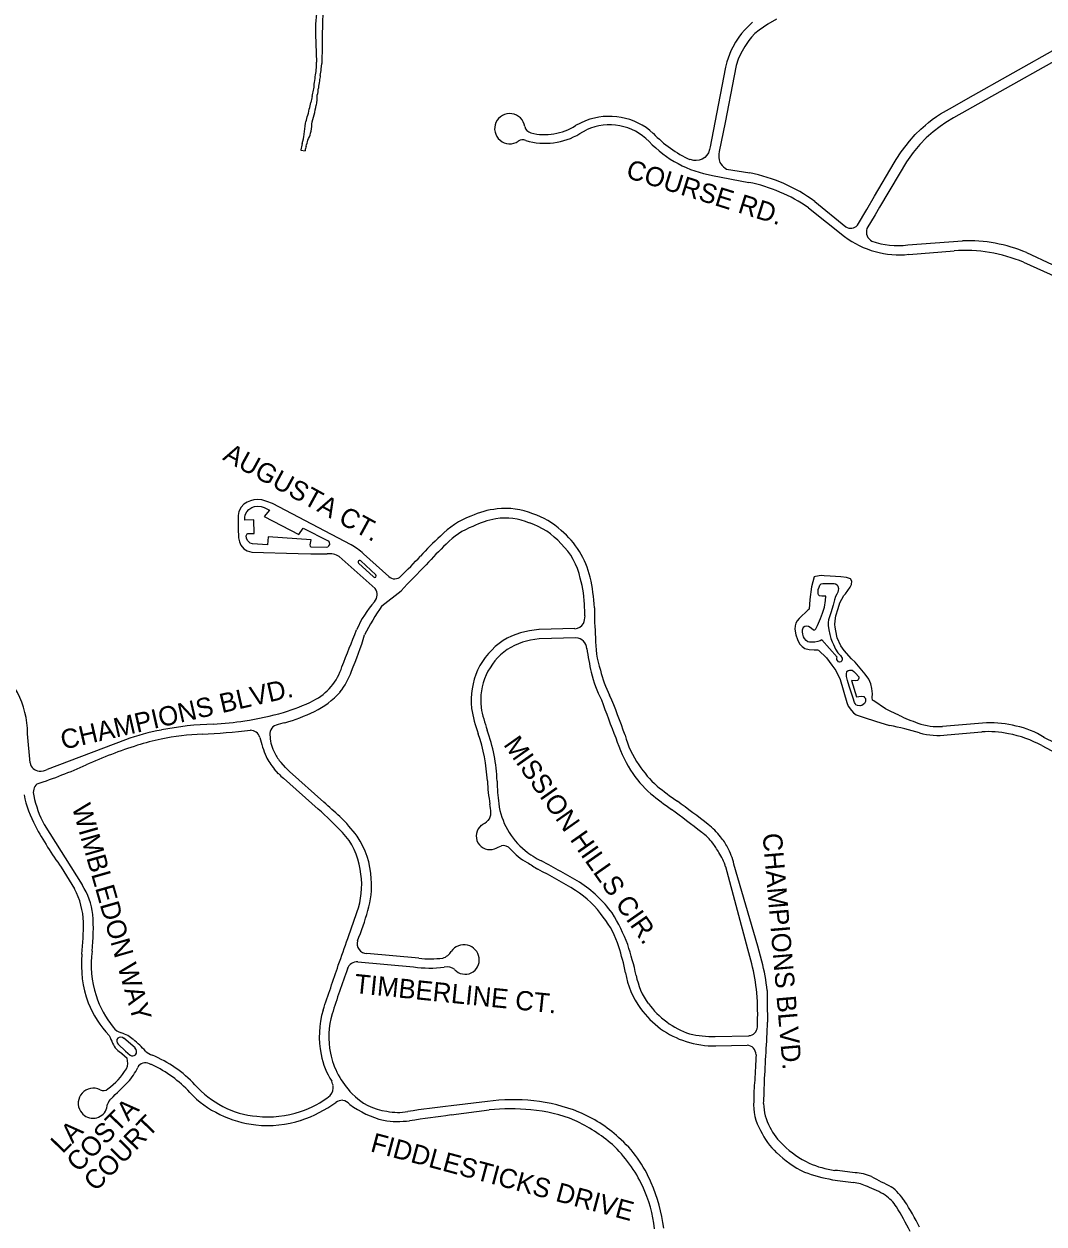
# Model space of a CAD drawing. Extents: x 0 to 712119, y 0 to 761125.
# Drawn here: x 661775 to 664425, y 720502 to 723620 of the extents above; entities that cross this region are included whole.
import ezdxf

# ---------------------------------------------------------------- set-up
doc = ezdxf.new("R2010")
doc.units = 0
doc.layers.add('PAVED ROADS', color=7, linetype='Continuous')
doc.layers.add('street names', color=7, linetype='Continuous')

msp = doc.modelspace()

# ---------------------------------------------------------------- linework, layer by layer
at = {"layer": 'PAVED ROADS'}
for points in [[(665392.5, 724053.4), (664578.7, 723594.7), (664190.1, 723375.9), (664170.3, 723364), (664155.6, 723353.4), (664137, 723340), (664119, 723324), (664102.5, 723306.5), (664085.5, 723286.5), (664067.5, 723261.5), (664048.5, 723230), (663998, 723144.5), (663986, 723124.5), (663965, 723088.5)], [(663668, 723625), (663655.5, 723612.5), (663647, 723604), (663639.5, 723595.5), (663632.5, 723586), (663623.5, 723572.5), (663616.5, 723560), (663611.5, 723550), (663607.5, 723541), (663604.5, 723531), (663601, 723521.5), (663597.5, 723508), (663570, 723364.5), (663557.5, 723301), (663556, 723293.5), (663553.5, 723285.5), (663549, 723279), (663544, 723273.5), (663536.5, 723268.5), (663529.5, 723266), (663521.5, 723265), (663515.5, 723265), (663505.3, 723267.6)], [(663729.6, 723632.3), (663707.8, 723619.7), (663695.9, 723612.1), (663684.6, 723603.6), (663673.9, 723594.9), (663665.4, 723585.9), (663658, 723577.2), (663647.5, 723561.5), (663637.3, 723543.2), (663630.6, 723528.6), (663625.5, 723512.1), (663619.7, 723485.4), (663596.5, 723364.5), (663581.5, 723289), (663580, 723282), (663580, 723273), (663581, 723267), (663583, 723260.5), (663585.5, 723256.5), (663588.5, 723252.5), (663592, 723248.5), (663597, 723245), (663600.5, 723243)], [(663940.5, 723097), (663965, 723138), (663985, 723173), (664036, 723259.5), (664041.1, 723268.2), (664054, 723288), (664066.5, 723304.5), (664075.5, 723315.5), (664090.5, 723333), (664105, 723347), (664116.8, 723357.2), (664124.9, 723364), (664134.4, 723371.7), (664145.6, 723379.6), (664155.8, 723386.8), (664179.1, 723400), (664205.7, 723414.4), (664227.7, 723427.6), (664578.6, 723624.7)], [(662532, 723592.5), (662535, 723520.5)], [(662547, 723503), (662549.1, 723517.2)], [(663233.8, 723368.6), (663208, 723356)], [(663219, 723335.2), (663236.6, 723345.1)], [(662494.2, 723292.3), (662505.5, 723290.5)], [(663600.5, 723243), (663660.5, 723233)], [(663564, 723226.5), (663658.5, 723208.5)], [(663829.5, 723159), (663910, 723093)], [(663813, 723142.5), (663907, 723067.5)], [(664071, 723046), (664213.5, 723056.5)], [(664074, 723021.5), (664191.5, 723031)], [(664379.5, 723026), (664512.5, 722964)], [(664372, 723001), (664510.5, 722939)], [(662625, 722267), (662420.5, 722374), (662406, 722379.5), (662393, 722383.5), (662382, 722384.5), (662372, 722383.5), (662363.5, 722381.5), (662354.5, 722377.5), (662346.5, 722372.5), (662339, 722364.5), (662333, 722353), (662331, 722343), (662331, 722330.5), (662331.5, 722310.5), (662332.5, 722285), (662334.5, 722275), (662338.5, 722265.5), (662346, 722256.5), (662355, 722251.5), (662366.5, 722247.5), (662487.5, 722244), (662520.5, 722243), (662562.5, 722243.5)], [(662722.5, 722184.5), (662657, 722243.5)], [(662594, 722236.5), (662687, 722153.5)], [(662683.1, 722183.3), (662644.2, 722218.9)], [(662649.9, 722225.1), (662689.1, 722189.2)], [(664048, 721824), (664027, 721833.5), (664013, 721840.5), (663983, 721861.5), (663979.5, 721863.5), (663978.5, 721870), (663979.5, 721879.5), (663977.5, 721893.5), (663975, 721905.5), (663970, 721917.5), (663960, 721931), (663947.5, 721946.5), (663934.5, 721961.5), (663924.5, 721971), (663906, 721992.5), (663897, 722004.5), (663888, 722025.5), (663884, 722043), (663882.5, 722052.5), (663882, 722059.5), (663882.5, 722069.5), (663884.5, 722082.5), (663890, 722101), (663895, 722116), (663899.5, 722125.5), (663905, 722135.5), (663909, 722139.5), (663921, 722156.5), (663925, 722164), (663926, 722172.5), (663922.7, 722178.5), (663911.5, 722182), (663897, 722183.5), (663869.5, 722185), (663853.5, 722186), (663846, 722187.5), (663831, 722184.5), (663827.5, 722183.5), (663821, 722157.5), (663817, 722124.5), (663814.5, 722100), (663812.5, 722097.5), (663788.5, 722075.5), (663784, 722069), (663780.5, 722063.5), (663778.5, 722056), (663778, 722047.5), (663780.5, 722033), (663784.5, 722020.5), (663790, 722009.5), (663796.5, 722003), (663804, 721997.5), (663815, 721995), (663828, 721994), (663836.5, 721994), (663839, 721993), (663859.5, 721973.5), (663873.5, 721954.5), (663884, 721940.5), (663895.5, 721916.5), (663913, 721857.5), (663916.5, 721848), (663924.5, 721836), (663930, 721830.5), (663937, 721825.5), (663957.5, 721818.5), (663987, 721808.5), (664024, 721797)], [(662705, 722108), (662754.5, 722147.5)], [(663206.5, 722049), (663113, 722046.5)], [(663209, 722025.5), (663113, 722022.5)], [(661791, 721700), (661784.5, 721776)], [(664276, 721804.5), (664161.5, 721795)], [(664173.5, 721773), (664263.5, 721781)], [(662038.5, 721760), (661835.5, 721683)], [(664419.5, 721745), (664482.5, 721711.5)], [(664512, 721724), (664425, 721766.5)], [(662436.6, 721672.2), (662425.3, 721685)], [(662454.5, 721688.1), (662443.1, 721700.9)], [(662539.5, 721580), (662449, 721660.3)], [(662553.6, 721598.2), (662465, 721678)], [(661827.4, 721539.8), (661926.2, 721383)], [(663692, 721185), (663681.5, 721224), (663619.5, 721437.5)], [(661871.8, 721429.1), (661906.3, 721372.7)], [(663666, 721178.5), (663655.5, 721216.5), (663598, 721429.9)], [(662642.5, 721183), (662787, 721170)], [(662800.5, 721192.5), (662665.5, 721205)], [(662005, 720972), (662005, 720972), (662005, 720972)], [(662020, 720969.5), (662038.9, 720951.4), (662050.5, 720940.5)], [(662063.4, 720960.1), (662034.7, 720984.6)], [(663570.5, 720989), (663658, 720991.5)], [(663572, 720965), (663653.5, 720967)], [(662029.6, 720945.1), (662042.8, 720933.1)], [(662578, 720862.5), (662576.5, 720866.5), (662574.5, 720873)], [(662979, 720820.5), (662884.5, 720809.5)], [(663696.5, 720815), (663696.5, 720815)], [(662884.5, 720785.5), (662983.5, 720799)]]:
    msp.add_lwpolyline(points, dxfattribs=at)
for points in [[(662408, 722267), (662369, 722269), (662362.5, 722271.5), (662356, 722278), (662353, 722284.5), (662352.5, 722290), (662355, 722295), (662356.5, 722296), (662373, 722296.5), (662372, 722332), (662348.5, 722331), (662348.5, 722337.5), (662350, 722344.5), (662353.5, 722352.5), (662359.5, 722359), (662367, 722364), (662374, 722366.5), (662382.5, 722367.5), (662391.5, 722366.5), (662399, 722364), (662412.5, 722356.5), (662399, 722340.5), (662489, 722294), (662500, 722310), (662565, 722277.5), (662568, 722273.5), (662568.5, 722268), (662566.5, 722264), (662564, 722260.5), (662561, 722259.5), (662520.5, 722261), (662519.5, 722263.5), (662518.5, 722266.5), (662521.5, 722280), (662409.5, 722287.5)], [(663839.5, 722137), (663838.5, 722140), (663838, 722151), (663840.5, 722156.5), (663843, 722162), (663846.5, 722165.5), (663850, 722166.5), (663857, 722166.5), (663871, 722166.5), (663879.5, 722166.5), (663883.5, 722165.5), (663887.5, 722162.5), (663889.5, 722159), (663891, 722153), (663890.5, 722148), (663889.5, 722144), (663887, 722138.5), (663883.5, 722132.5), (663881, 722124), (663877, 722110), (663871, 722090), (663867.5, 722080), (663865, 722071.5), (663864.5, 722065), (663864.5, 722057.5), (663866, 722046), (663868.5, 722034), (663871.5, 722023.5), (663874.5, 722015), (663878, 722007.5), (663883.5, 721996), (663889, 721986.5), (663896, 721979), (663900.5, 721972.5), (663900.5, 721970), (663899.5, 721965.5), (663897.5, 721963), (663893.5, 721962), (663891.5, 721962.5), (663888.5, 721966), (663887, 721968.5), (663886.5, 721971), (663887, 721973.5), (663888, 721974.5), (663848, 722020), (663843.5, 722017.5), (663837.5, 722015.5), (663830, 722013.5), (663823.5, 722013.5), (663816, 722013.5), (663811, 722015), (663807.5, 722018), (663803, 722023), (663800.5, 722028), (663798.5, 722035), (663797.5, 722041), (663797.5, 722046), (663799, 722051), (663801, 722054), (663804, 722055.5), (663808.5, 722056), (663813, 722055.5), (663817.5, 722053), (663825, 722046.5), (663827, 722045.5), (663830, 722046), (663832.5, 722048.5), (663836.5, 722057), (663844, 722075), (663849.5, 722089.5), (663854.5, 722104.5), (663857.5, 722122), (663858.5, 722133), (663857, 722133.5), (663848, 722133.5), (663842, 722134), (663840.5, 722135.5)], [(663932.5, 721857.5), (663929, 721868.5), (663924.5, 721881.5), (663918.5, 721899.5), (663914.5, 721914), (663912, 721924.5), (663911.5, 721930.5), (663913, 721937.5), (663916, 721940.5), (663920, 721941.5), (663927, 721941), (663931, 721937.5), (663935, 721933.5), (663944, 721923.5), (663944, 721920.5), (663942.5, 721916), (663940.5, 721914), (663935, 721913), (663925, 721914), (663938, 721872), (663944, 721873), (663950.5, 721874), (663957, 721872.5), (663959, 721870.5), (663961, 721867.5), (663961.5, 721863), (663961, 721859.5), (663958.5, 721854.5), (663955.5, 721852), (663951.5, 721849.5), (663948.5, 721848.5), (663946.5, 721848.5), (663940.5, 721849.5), (663936.5, 721851.1), (663934, 721854.5)]]:
    msp.add_lwpolyline(points, close=True, dxfattribs=at)
for centre, radius, start, end in [((663175.7, 723588.9), 643.7, 173.2135, 179.683), ((670799.9, 723454.1), 8251.1, 178.68106, 179.56146), ((662372.2, 723516.8), 162.8, 348.0269, 1.3088), ((662480.4, 723504.7), 66.6, 344.1902, 358.5785), ((662474.8, 723462.6), 54.2, 344.3565, 0.9388), ((662284.9, 723504.7), 247.6, 350.4187, 354.9698), ((662650.1, 723448), 110.3, 167.4478, 177.1601), ((663213.6, 723386.8), 676.4, 171.5268, 172.7666), ((662706.3, 723377.9), 190.2, 163.4785, 168.449), ((662322.3, 723478.1), 206.9, 347.1261, 351.6345), ((662395.9, 723436), 141.1, 349.1906, 359.6107), ((662443.3, 723459.7), 96.9, 345.2405, 356.3374), ((662319.1, 723437.1), 200.7, 343.0192, 348.9084), ((662449.8, 723422.8), 70.6, 339.8163, 354.4337), ((662037.3, 723507.7), 506.8, 345.8582, 348.825), ((660339, 724027.7), 2267, 342.9237, 343.3595), ((661030.6, 723757.7), 1544.1, 345.0548, 345.991), ((663037, 723348.1), 39.3, 7.8414, 303.9541), ((663295.6, 723209.9), 170.2, 47.7686, 111.2583), ((662363.8, 723364.1), 142.2, 347.5077, 359.1547), ((662453.6, 723352.7), 68, 329.2897, 345.7796), ((662446.9, 723357), 75.6, 343.8548, 1.8517), ((663098.6, 723359.4), 23.4, 194.6889, 253.5483), ((663129, 723484.1), 174, 253.3031, 301.1412), ((663127.7, 723482.6), 149.9, 256.2236, 302.3805), ((663296.1, 723214.5), 143.5, 44.1836, 114.4686), ((663632.2, 723545.1), 305.2, 223.2558, 245.4124), ((663276, 723145), 795.6, 168.0462, 169.2977), ((662386.7, 723345.4), 116.6, 342.1777, 354.0424), ((662425.4, 723332.4), 87.9, 340.11, 350.5657), ((663070.7, 723299), 20.2, 65.8991, 125.5221), ((663612.8, 723516.8), 294.3, 223.4062, 260.4488), ((662807.6, 723233.5), 318.9, 169.2969, 169.3746), ((662544.1, 723288.7), 38.7, 159.1157, 177.3478), ((663581.8, 722823.3), 417.1, 53.5771, 79.1285), ((663573.2, 722794.9), 422.3, 55.395, 78.3421), ((663922.9, 723112.7), 23.5, 236.6953, 318.2478), ((663991.3, 723079.8), 27.7, 161.6253, 241.3775), ((664048.6, 723255.5), 235.3, 233.0058, 276.1939), ((664044.8, 723249.8), 205.5, 251.0213, 277.3136), ((664227.9, 722667.8), 389, 67.0588, 92.119), ((664216.9, 722625.7), 406.1, 67.5451, 93.5817), ((663005.1, 722151.8), 201.9, 110.0182, 137.1944), ((663024.6, 722150.1), 210.9, 95.6013, 114.8376), ((663026.8, 722177.1), 184.3, 67.5965, 97.0931), ((663029.4, 722148.7), 210, 47.7437, 71.2039), ((663000.7, 722150.2), 174.8, 109.9682, 137.4119), ((663041.4, 722113.2), 224.9, 100.3529, 116.517), ((663025.1, 722175.2), 161.1, 67.002, 98.5859), ((663031, 722146.5), 186, 41.4071, 72.1436), ((663235.2, 721858.8), 572.9, 131.32, 138.68), ((663023.5, 722128.7), 228.9, 13.5949, 50.0352), ((662566.7, 722188), 55.6, 60.6065, 94.3359), ((662510.4, 722077.5), 221.5, 48.5645, 58.8503), ((663419.9, 721683.9), 801.2, 133.146, 138.4832), ((663052, 722145.4), 171.6, 11.6221, 46.305), ((662647, 722222.1), 4.21, 46.3753, 228.6412), ((659141.5, 725779.1), 5095.9, 315.1468, 315.9657), ((667118.9, 717978), 6036, 135.41511, 136.30794), ((662686.1, 722186.2), 4.21, 224.5552, 44.4183), ((662738, 722201.4), 22.9, 227.4976, 314.3212), ((662780.7, 722077.4), 477.1, 3.1315, 12.7224), ((662666, 722137.1), 26.6, 317.0971, 37.9238), ((662957.7, 722103.2), 273.3, 359.9492, 16.311), ((662904.1, 721928.5), 289.9, 138.9196, 156.0872), ((663240.2, 721735.9), 651.9, 145.1895, 152.883), ((663078.4, 722081.5), 154.1, 0.1699, 8.0013), ((663999.9, 722093.4), 742.9, 179.2248, 185.2088), ((663203.6, 722078.3), 29.5, 275.5539, 327.5156), ((663161.4, 722086.4), 71.3, 340.378, 356.4377), ((654271.7, 725302.5), 8978.6, 338.07526, 338.73412), ((661793.1, 722295.9), 905.9, 336.7607, 343.1271), ((663124.1, 721842.4), 204.4, 93.1187, 120.7851), ((663207.6, 721996.1), 29.4, 1.7083, 87.2777), ((663509.7, 722019.3), 249.8, 178.4639, 198.2678), ((663130.9, 721855.2), 197.3, 124.3771, 154.0512), ((663123, 721862.1), 161.6, 124.9479, 186.4226), ((663127, 721845.7), 177.3, 94.5281, 122.9657), ((664218.2, 722148.7), 992.8, 188.7859, 192.3971), ((661553.1, 721774.9), 231.4, 0.2771, 55.2524), ((662460.5, 721993), 146.9, 296.9026, 342.9758), ((662459.7, 721993), 174.5, 321.3466, 341.8014), ((663144.2, 721859.8), 207.5, 156.8081, 184.9215), ((663585, 722019.6), 346.9, 194.0261, 206.6463), ((663545, 722005.7), 280.1, 193.3521, 207.4677), ((662438.5, 722024.3), 210.9, 295.5628, 318.3148), ((661365.8, 721074.2), 2090.8, 19.5105, 22.5645), ((662312.7, 722292.8), 481.1, 286.5165, 296.4476), ((663363.9, 721919.7), 433.4, 190.3322, 199.3685), ((663341.4, 721916.2), 385.7, 190.7873, 199.8058), ((670991, 724730.1), 8231.1, 200.37762, 201.11454), ((662233.4, 722518.6), 718.3, 272.6845, 279.2237), ((662213.4, 722672.7), 873.7, 278.897, 285.6796), ((662324.6, 722251.3), 464.9, 286.0284, 296.147), ((664302.4, 722368.3), 600.8, 244.9481, 250.059), ((662217.3, 721291.4), 501.5, 99.7786, 110.8855), ((662292, 720980), 821.4, 91.7453, 101.226), ((662122.8, 723895.7), 2124.3, 273.1097, 276.4935), ((662363.2, 721759.8), 25.2, 15.4539, 90.433), ((662437.5, 721775.5), 24.2, 107.98, 198.1409), ((662503.4, 721564.3), 245.4, 101.8449, 107.3968), ((662524.2, 721628), 455.5, 3.2094, 18.9604), ((662564.1, 721637.1), 440.2, 2.0766, 19.7105), ((663940.6, 721289.4), 514.4, 71.7766, 80.6734), ((664149.9, 721953), 158.4, 250.6772, 274.1922), ((664150.5, 721962.1), 190.5, 255.1097, 276.9454), ((664278, 721497.7), 283.7, 78.8308, 92.9394), ((664284.2, 721529.6), 275, 75.6155, 91.7042), ((664275.1, 721478.3), 303.3, 61.5707, 78.9958), ((664308.4, 721583.8), 216.8, 57.4581, 78.2594), ((662443.3, 720572.1), 1231.9, 107.6655, 114.294), ((662249, 721163.7), 609.3, 101.1623, 107.1292), ((662242.7, 721288.7), 485.8, 90.5583, 103.2961), ((662784.4, 721871.3), 410.5, 194.7912, 202.0787), ((662509.6, 721771.9), 95.2, 182.3601, 209.1743), ((663665.7, 721875.6), 370.1, 197.3804, 211.6461), ((663548.1, 721824.4), 217.9, 193.7795, 216.3381), ((662524.3, 721773.9), 133.1, 205.3255, 221.9236), ((662515.6, 721767.7), 98.6, 205.3549, 222.6989), ((661816, 721704.3), 25.4, 189.853, 266.5779), ((661347.5, 723023.2), 1452.9, 288.5202, 293.9158), ((661817.4, 721720.8), 41.9, 265.9966, 295.572), ((662493.8, 721718.9), 50, 218.0248, 234.7306), ((663604.9, 721845.7), 276.8, 212.9248, 227.9781), ((662485.5, 721710.5), 62.1, 218.019, 233.9344), ((663438, 721672.2), 459.4, 182.3347, 189.9297), ((663545.3, 721665.2), 541.5, 181.2929, 187.5045), ((663602.8, 721844.2), 300.1, 212.8495, 228.4025), ((661827.6, 721623.9), 28.5, 130.6539, 198.201), ((664044, 722415.5), 1021.5, 231.1726, 234.927), ((663993.9, 722351.2), 914, 231.0764, 235.2183), ((662064.5, 721676.6), 295.4, 191.5352, 208.376), ((662069.8, 721668.8), 274.6, 191.3026, 208.0171), ((645001.9, 701647.2), 26572.6, 48.53903, 48.66056), ((662699.1, 721549.3), 289.7, 4.293, 8.6732), ((663193.4, 721618.1), 186.4, 187.2644, 231.3619), ((661065.7, 718308.1), 4078.3, 52.4276, 53.8326), ((661873.9, 720822.5), 1008.4, 43.7348, 48.6925), ((662254.1, 721219.4), 483.2, 36.9326, 44.9801), ((662961.5, 721569.1), 26.6, 315.6896, 4.1199), ((659168.8, 715840.8), 7163.9, 52.4402, 53.23121), ((662631.8, 721981.3), 939.4, 208.2861, 216.0022), ((662985.4, 721510.4), 35.5, 128.9934, 289.9893), ((662827, 721746.8), 249.2, 303.0646, 308.0107), ((663424.1, 721381.1), 204.7, 38.2388, 51.1528), ((662475.7, 721399.7), 174.5, 7.9977, 43.402), ((662467, 721390.9), 210.1, 2.1978, 34.4306), ((663453.5, 721407.1), 139.6, 37.3801, 53.8366), ((663474.8, 721416.1), 143.3, 26.9254, 39.7686), ((662834.9, 721867.1), 422.6, 292.6272, 295.2978), ((663020.2, 721461.6), 23.9, 40.1992, 101.4428), ((663147.1, 721566.6), 140.8, 219.518, 242.6876), ((663210.8, 721636.1), 211.4, 230.7322, 244.4127), ((663421.1, 721382.5), 180.2, 28.1551, 37.3539), ((663474.7, 721394.1), 128.3, 16.1894, 34.8723), ((663452.6, 721397.3), 171.7, 13.5274, 29.1641), ((670282.3, 732725.1), 13384.9, 237.45904, 237.59857), ((662009.7, 719349.8), 2371.4, 59.3535, 62.096), ((662434.3, 721383.5), 218, 344.1521, 10.6947), ((662156.7, 719620.1), 2040.4, 59.0006, 62.1445), ((661739.5, 721281.5), 190, 1.349, 28.6681), ((661763, 721280.5), 192.7, 7.638, 32.1336), ((662454.2, 721380.3), 223.6, 343.4279, 4.8072), ((663044.4, 721121), 320.4, 36.2458, 57.0918), ((663072.2, 721156.3), 252.1, 34.4749, 57.5352), ((479569.9, 785355), 193948.7, 340.697434, 340.722473), ((661814.8, 721566.2), 889.5, 338.3448, 343.694), ((662894.9, 721057.9), 479.8, 20.7594, 31.754), ((661242.9, 721277.5), 686.6, 353.7718, 0.71), ((661423.9, 721271.5), 531.3, 353.5098, 3.7356), ((663116.5, 721164.8), 211.5, 15.8283, 39.3796), ((660302.5, 722020.5), 2440.3, 339.7164, 341.4467), ((662666.1, 721230.6), 25.6, 163.307, 268.7477), ((662918, 721188), 39.9, 7.9178, 145.6893), ((662892.4, 721075.6), 452.1, 10.1112, 18.9577), ((662500.7, 720953.2), 886.5, 12.694, 18.0585), ((662211.9, 721175.4), 287.8, 174.4869, 199.9869), ((662208.4, 721176.4), 259, 172.2177, 198.1598), ((662640.2, 721156.5), 26.6, 84.9765, 161.4366), ((662829.7, 721482), 290.9, 264.2386, 276.6709), ((662851.5, 721229.7), 38.6, 288.1243, 330.1636), ((662921.1, 721187.9), 36.8, 222.6362, 8.6752), ((663217.1, 721058.6), 491.4, 5.8325, 14.909), ((614548.4, 737398.8), 50708.7, 341.20098, 341.33997), ((665854.7, 720006.1), 3440.7, 160.3167, 162.3732), ((662828.9, 721470.1), 303, 262.0555, 277.2283), ((662873.6, 721137.6), 32.6, 51.22, 101.7083), ((663551.4, 721191), 216.9, 189.543, 216.4819), ((662921.3, 721012), 763.1, 6.8108, 12.6025), ((663537.1, 721178.7), 174.3, 190.1556, 216.5254), ((662206.2, 721174), 256.2, 197.8126, 218.8273), ((662899.6, 721045), 781.5, 357.7247, 4.2173), ((665242.7, 721086.2), 1536.8, 179.1699, 182.2275), ((662194.2, 721180.2), 272.9, 202.2169, 223.5936), ((663564, 721195.9), 230, 215.6095, 252.5381), ((663577.2, 721208), 223.9, 216.4384, 251.0042), ((662779.2, 720990.3), 237, 163.4074, 191.635), ((662777.5, 720988), 210.7, 163.4526, 191.4951), ((662037.1, 721035.7), 37.8, 216.1248, 256.0077), ((661999.6, 720913.7), 89.9, 48.6109, 71.5756), ((663572.5, 721312.4), 323.4, 257.8269, 269.6518), ((663656.6, 721015.4), 23.9, 273.247, 356.753), ((647174.5, 721846), 16552.8, 356.61989, 357.1624), ((662691.4, 721275.5), 750.5, 202.1959, 203.855), ((662059.5, 720997.2), 60, 204.8319, 240.1677), ((662027.8, 720978.1), 11.6, 143.3824, 227.6726), ((662026.3, 720974.1), 13.4, 51.206, 125.754), ((661936.7, 720822), 200.8, 39.9944, 52.4564), ((663566.4, 721190.7), 225.8, 251.5786, 271.4327), ((663651.3, 720941.4), 25.7, 1.3341, 85.123), ((662056.9, 720951.9), 13.1, 240.752, 306.6223), ((662053.9, 720950.1), 13.8, 321.2066, 46.8854), ((662142.3, 721019.2), 85.6, 232.7544, 246.7327), ((661983.5, 720641.5), 324.1, 43.3501, 67.3209), ((662751.7, 720983.3), 208.8, 191.2757, 211.9001), ((662780.3, 720990.8), 214.1, 192.0674, 224.2764), ((668838.6, 720637), 5170.6, 176.6183, 177.3562), ((661873.2, 721012.3), 199.3, 306.9402, 327.5957), ((662002.1, 720921.2), 42.4, 338.3077, 16.2588), ((661929.9, 720975.8), 155.7, 317.686, 334.5866), ((662090.4, 720898.8), 22.4, 61.7575, 152.8436), ((662044.1, 720776.1), 153.3, 65.3785, 68.2243), ((661979.7, 720637.8), 305.9, 42.3784, 65.2116), ((664002.3, 720836.3), 331.1, 173.1988, 182.559), ((661955.1, 720815.9), 39.2, 63.6455, 212.2671), ((661981.2, 720867.8), 18.9, 242.5846, 308.5598), ((658055.5, 724862.4), 5643.4, 314.3585, 314.9867), ((662381.5, 721003.3), 237.2, 222.1825, 245.7286), ((662411, 721036.2), 257.8, 221.9194, 242.3406), ((662549.2, 720856.3), 29.4, 316.3152, 12.0798), ((662735.8, 720942.5), 148.5, 222.9189, 263.0987), ((662968.9, 720869), 729.6, 355.756, 0.0789), ((661936.1, 720819.3), 56.2, 334.9059, 354.0459), ((662029.2, 720799.5), 39.8, 135.1872, 159.3424), ((662413.9, 721034.3), 252.7, 288.3547, 308.2912), ((662390.1, 721089.3), 334.3, 288.3773, 305.7668), ((662604.4, 720788.6), 35, 92.2435, 122.6509), ((662596.1, 720789.8), 34.3, 42.3823, 78.462), ((662764.4, 721001.3), 236.3, 232.8028, 256.4485), ((663257.1, 717585.5), 3245.4, 96.5928, 98.5965), ((663047.7, 720309.5), 515.6, 84.2393, 97.6625), ((663048.5, 720373.5), 451.9, 68.1756, 83.5216), ((663784.7, 720806.8), 114.1, 172.6198, 212.8607), ((663829.7, 720817.3), 133.2, 181.0037, 208.391), ((661954.3, 720815), 38, 211.7459, 329.1355), ((662414.6, 721057.7), 300.6, 244.244, 262.8102), ((662399.5, 721014), 232.8, 242.3156, 265.1857), ((662408.7, 721043), 262.5, 263.7249, 288.8447), ((662746.2, 720927.5), 135.4, 257.97, 280.969), ((666966.8, 691136), 29929.2, 97.83958, 98.04737), ((663037.8, 720211.9), 589.6, 84.7204, 95.2796), ((663057.9, 720407.8), 392.7, 67.8504, 85.0251), ((663085, 720473.8), 345.2, 47.1757, 67.6157), ((662406.4, 721048.9), 290.9, 264.2024, 287.8407), ((662746.4, 721005.1), 236.5, 260.8923, 277.4227), ((663020.3, 720376.8), 436.2, 49.4966, 64.8032), ((663862.2, 720829.3), 167.6, 206.7072, 227.0211), ((663115.2, 720490.9), 312.4, 22.2362, 49.1008), ((663845.4, 720814.3), 171.2, 203.8816, 227.7839), ((663066.7, 720453.3), 348.1, 24.8722, 47.128), ((663931.4, 720897.9), 291, 226.2994, 243.6962), ((663917.6, 720881.1), 243.3, 225.7901, 245.0533), ((663914.6, 720883.1), 243.9, 245.9026, 262.2066), ((663961.1, 721079.1), 469.7, 250.2564, 259.4818), ((663760.3, 719347.9), 1299.2, 82.315, 84.6454), ((663924.3, 720501.7), 134.2, 67.0907, 85.8469), ((672171.2, 736656.4), 18004.1, 242.92515, 243.1096), ((663055.1, 720449.2), 360.4, 6.4526, 24.6887), ((663024.3, 720440.3), 415.8, 6.9939, 23.9478), ((663995.2, 721348.2), 740.8, 260.6915, 264.9139), ((663906.4, 720464.7), 147.5, 66.1442, 80.9741), ((663840.1, 720280.5), 343.1, 59.7864, 68.4679), ((663921.8, 720464.5), 171.5, 34.5461, 51.6462), ((663946.9, 720484.9), 113.2, 33.255, 54.4381), ((663550.1, 720225.6), 613.2, 25.9648, 33.2409), ((663190.1, 720033.2), 994.5, 26.8893, 31.1059)]:
    msp.add_arc(centre, radius, start, end, dxfattribs=at)

# ---------------------------------------------------------------- texts
at = {"layer": 'street names'}
for s, rotation, p in [('COURSE RD.', 342.6961, (663336.2, 723221.6)), ('AUGUSTA CT.', 331.3496, (662288.9, 722489.1)), ('CHAMPIONS BLVD.', 12.96, (661876.5, 721734.3)), ('MISSION HILLS CIR.', 305.0717, (663019.1, 721747.7)), ('WIMBLEDON WAY', 285.9838, (661898.9, 721586.1)), ('CHAMPIONS BLVD.', 274.8963, (663693.8, 721515.9)), ('TIMBERLINE CT.', 354.1987, (662631.6, 721102.4)), ('COSTA', 45.6898, (661916.2, 720634.3)), ('COURT', 45.6898, (661961, 720584.5)), ('LA', 45.6898, (661875.2, 720683.1)), ('FIDDLESTICKS DRIVE', 344.9838, (662672.7, 720691.5))]:
    msp.add_text(s, height=50, rotation=rotation, dxfattribs=at).set_placement(p)

doc.saveas('drawing.dxf')
